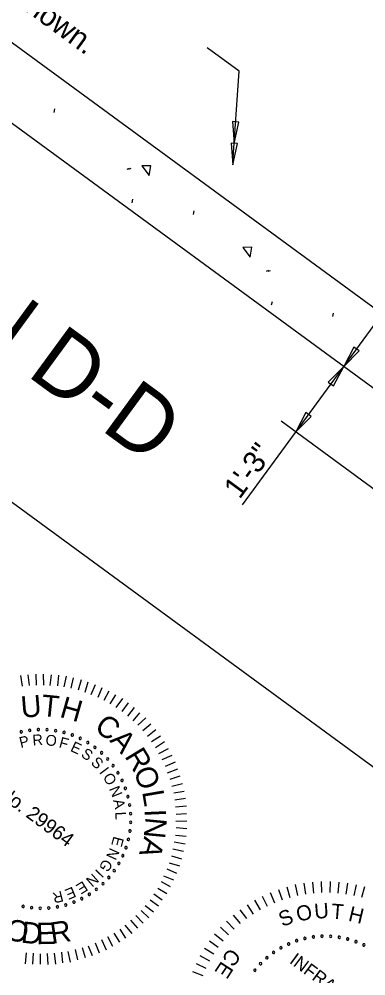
# Model space of a CAD drawing. Extents: x 1970731 to 1970899, y 796145 to 796301.
# Drawn here: x 1970813.63 to 1970821.64, y 796175.27 to 796197.36 of the extents above; entities that cross this region are included whole.
import ezdxf

# ---------------------------------------------------------------- set-up
doc = ezdxf.new("R2010")
doc.units = 0
for name, color, linetype in [('BR_AUTO DIMENSION', 7, 'Continuous'), ('BR_BORDER LINES', 7, 'Continuous'), ('BR_CONCRETE', 7, 'Continuous'), ('BR_DETAILS', 7, 'Continuous'), ('BR_TEXT', 7, 'Continuous')]:
    doc.layers.add(name, color=color, linetype=linetype)

msp = doc.modelspace()

# ---------------------------------------------------------------- linework, layer by layer
at = {"layer": 'BR_AUTO DIMENSION'}
for p, q in [((1970818.708, 796196.161), (1970817.972, 796196.699)), ((1970818.567, 796194.051), (1970818.708, 796196.16)), ((1970818.787, 796186.151), (1970823.376, 796192.419)), ((1970824.464, 796184.573), (1970819.679, 796188.077))]:
    msp.add_line(p, q, dxfattribs=at)
for points in [[(1970818.555, 796194.996), (1970818.596, 796194.492), (1970818.704, 796194.986)], [(1970818.522, 796194.501), (1970818.564, 796193.997), (1970818.672, 796194.491)], [(1970821.359, 796189.791), (1970821.124, 796189.343), (1970821.48, 796189.703)], [(1970820.889, 796188.895), (1970821.123, 796189.343), (1970820.768, 796188.984)], [(1970820.251, 796188.278), (1970820.016, 796187.831), (1970820.372, 796188.19)]]:
    msp.add_lwpolyline(points, close=True, dxfattribs=at)
at = {"layer": 'BR_BORDER LINES'}
msp.add_line((1970811.99, 796187.287), (1970829.306, 796174.609), dxfattribs=at)
at = {"layer": 'BR_CONCRETE'}
for p, q in [((1970827.934, 796186.216), (1970803.754, 796203.919)), ((1970827.073, 796184.987), (1970802.867, 796202.709)), ((1970827.073, 796184.987), (1970802.867, 796202.709))]:
    msp.add_line(p, q, dxfattribs=at)
at = {"layer": 'BR_DETAILS'}
for p, q in [((1970814.436, 796195.209), (1970814.453, 796195.289)), ((1970816.171, 796193.914), (1970816.114, 796193.894)), ((1970816.209, 796193.91), (1970816.153, 796193.889)), ((1970816.241, 796193.122), (1970816.258, 796193.202)), ((1970817.653, 796192.853), (1970817.671, 796192.933)), ((1970819.389, 796191.559), (1970819.332, 796191.538)), ((1970819.427, 796191.554), (1970819.37, 796191.534)), ((1970819.458, 796190.766), (1970819.476, 796190.846)), ((1970820.871, 796190.497), (1970820.888, 796190.577))]:
    msp.add_line(p, q, dxfattribs=at)
for points in [[(1970816.63, 796193.751), (1970816.672, 796193.978), (1970816.464, 796193.976), (1970816.63, 796193.751)], [(1970818.961, 796191.868), (1970819.004, 796192.095), (1970818.795, 796192.093), (1970818.961, 796191.868)]]:
    msp.add_lwpolyline(points, dxfattribs=at)
at = {"layer": 'BR_TEXT'}
for p, q in [((1970813.706, 796181.962), (1970813.668, 796182.209)), ((1970813.866, 796181.981), (1970813.837, 796182.224)), ((1970814.03, 796181.983), (1970814.019, 796182.239)), ((1970814.199, 796181.985), (1970814.193, 796182.242)), ((1970814.349, 796181.98), (1970814.379, 796182.227)), ((1970814.519, 796181.973), (1970814.549, 796182.22)), ((1970814.672, 796181.949), (1970814.72, 796182.191)), ((1970814.832, 796181.916), (1970814.888, 796182.152)), ((1970814.997, 796181.879), (1970815.067, 796182.117)), ((1970815.154, 796181.826), (1970815.22, 796182.063)), ((1970815.294, 796181.772), (1970815.396, 796182.001)), ((1970815.451, 796181.707), (1970815.546, 796181.932)), ((1970815.596, 796181.638), (1970815.711, 796181.855)), ((1970815.733, 796181.557), (1970815.865, 796181.763)), ((1970815.866, 796181.471), (1970816.02, 796181.677)), ((1970816.007, 796181.379), (1970816.154, 796181.577)), ((1970816.136, 796181.27), (1970816.295, 796181.472)), ((1970816.259, 796181.165), (1970816.418, 796181.35)), ((1970816.372, 796181.059), (1970816.551, 796181.23)), ((1970816.483, 796180.938), (1970816.669, 796181.095)), ((1970816.591, 796180.807), (1970816.786, 796180.965)), ((1970816.685, 796180.686), (1970816.891, 796180.819)), ((1970816.78, 796180.55), (1970816.989, 796180.686)), ((1970816.855, 796180.409), (1970817.076, 796180.522)), ((1970816.93, 796180.267), (1970817.162, 796180.373)), ((1970817.008, 796180.119), (1970817.239, 796180.217)), ((1970817.058, 796179.962), (1970817.294, 796180.056)), ((1970817.114, 796179.814), (1970817.35, 796179.89)), ((1970817.157, 796179.653), (1970817.405, 796179.716)), ((1970817.199, 796179.497), (1970817.443, 796179.538)), ((1970817.224, 796179.342), (1970817.467, 796179.379)), ((1970817.242, 796179.175), (1970817.493, 796179.197)), ((1970817.251, 796178.843), (1970817.502, 796178.852)), ((1970817.254, 796179.007), (1970817.495, 796179.021)), ((1970817.253, 796178.696), (1970817.498, 796178.675)), ((1970817.212, 796178.371), (1970817.462, 796178.321)), ((1970817.236, 796178.524), (1970817.483, 796178.499)), ((1970817.181, 796178.209), (1970817.423, 796178.154)), ((1970817.144, 796178.044), (1970817.377, 796177.978)), ((1970817.039, 796177.742), (1970817.266, 796177.645)), ((1970817.092, 796177.882), (1970817.33, 796177.816)), ((1970816.966, 796177.587), (1970817.196, 796177.493)), ((1970816.831, 796177.302), (1970817.043, 796177.178)), ((1970816.907, 796177.45), (1970817.116, 796177.334)), ((1970819.617, 796177.27), (1970819.7, 796177.03)), ((1970819.809, 796177.331), (1970819.878, 796177.086)), ((1970820.005, 796177.38), (1970820.059, 796177.131)), ((1970820.204, 796177.416), (1970820.243, 796177.164)), ((1970820.404, 796177.441), (1970820.428, 796177.187)), ((1970820.606, 796177.453), (1970820.614, 796177.198)), ((1970820.808, 796177.452), (1970820.8, 796177.198)), ((1970821.009, 796177.44), (1970820.986, 796177.186)), ((1970821.21, 796177.415), (1970821.171, 796177.163)), ((1970821.408, 796177.378), (1970821.354, 796177.129)), ((1970821.604, 796177.329), (1970821.535, 796177.084)), ((1970816.742, 796177.171), (1970816.935, 796177.028)), ((1970819.244, 796177.115), (1970819.357, 796176.886)), ((1970819.428, 796177.198), (1970819.526, 796176.964)), ((1970816.541, 796176.902), (1970816.73, 796176.752)), ((1970816.652, 796177.033), (1970816.847, 796176.888)), ((1970818.893, 796176.915), (1970819.033, 796176.702)), ((1970819.066, 796177.02), (1970819.192, 796176.799)), ((1970816.323, 796176.666), (1970816.49, 796176.494)), ((1970816.443, 796176.782), (1970816.62, 796176.611)), ((1970818.569, 796176.674), (1970818.734, 796176.48)), ((1970818.728, 796176.8), (1970818.88, 796176.596)), ((1970816.073, 796176.445), (1970816.231, 796176.255)), ((1970816.201, 796176.56), (1970816.361, 796176.372)), ((1970818.277, 796176.396), (1970818.464, 796176.223)), ((1970818.419, 796176.539), (1970818.595, 796176.355)), ((1970815.672, 796176.183), (1970815.788, 796175.96)), ((1970815.816, 796176.261), (1970815.946, 796176.056)), ((1970815.952, 796176.352), (1970816.085, 796176.146)), ((1970818.144, 796176.244), (1970818.341, 796176.082)), ((1970815.223, 796175.97), (1970815.315, 796175.743)), ((1970815.382, 796176.035), (1970815.477, 796175.806)), ((1970815.528, 796176.111), (1970815.641, 796175.877)), ((1970818.021, 796176.084), (1970818.228, 796175.935)), ((1970813.793, 796175.803), (1970813.765, 796175.554)), ((1970813.953, 796175.795), (1970813.935, 796175.547)), ((1970814.112, 796175.783), (1970814.113, 796175.543)), ((1970814.278, 796175.788), (1970814.294, 796175.54)), ((1970814.441, 796175.795), (1970814.468, 796175.544)), ((1970814.604, 796175.823), (1970814.633, 796175.575)), ((1970814.756, 796175.838), (1970814.809, 796175.593)), ((1970814.924, 796175.88), (1970814.979, 796175.643)), ((1970815.081, 796175.93), (1970815.15, 796175.695)), ((1970817.805, 796175.743), (1970818.028, 796175.62)), ((1970817.908, 796175.916), (1970818.123, 796175.78)), ((1970817.713, 796175.563), (1970817.943, 796175.454)), ((1970817.632, 796175.378), (1970817.868, 796175.283))]:
    msp.add_line(p, q, dxfattribs=at)
for centre, start, end in [((1970813.677, 796180.908), 13.1636, 193.1636), ((1970813.677, 796180.908), 193.1636, 13.1636), ((1970813.874, 796180.943), 7.6251, 187.6251), ((1970813.874, 796180.943), 187.6251, 7.6251), ((1970814.072, 796180.96), 2.0866, 182.0866), ((1970814.072, 796180.96), 182.0866, 2.0866), ((1970814.271, 796180.957), 356.5482, 176.5482), ((1970814.271, 796180.957), 176.5482, 356.5482), ((1970814.47, 796180.935), 351.0097, 171.0097), ((1970814.47, 796180.935), 171.0097, 351.0097), ((1970814.665, 796180.894), 345.4713, 165.4713), ((1970814.665, 796180.894), 165.4713, 345.4713), ((1970814.855, 796180.834), 159.9328, 339.9328), ((1970814.855, 796180.834), 339.9328, 159.9328), ((1970815.038, 796180.757), 154.3943, 334.3943), ((1970815.038, 796180.757), 334.3943, 154.3943), ((1970815.214, 796180.661), 148.8559, 328.8559), ((1970815.214, 796180.661), 328.8559, 148.8559), ((1970815.379, 796180.55), 323.3174, 143.3174), ((1970815.379, 796180.55), 143.3174, 323.3174), ((1970815.532, 796180.423), 137.779, 317.779), ((1970815.532, 796180.423), 317.779, 137.779), ((1970815.673, 796180.282), 132.2405, 312.2405), ((1970815.673, 796180.282), 312.2405, 132.2405), ((1970815.799, 796180.128), 126.702, 306.702), ((1970815.799, 796180.128), 306.702, 126.702), ((1970815.91, 796179.962), 121.1636, 301.1636), ((1970815.91, 796179.962), 301.1636, 121.1636), ((1970816.005, 796179.786), 115.6251, 295.6251), ((1970816.005, 796179.786), 295.6251, 115.6251), ((1970816.082, 796179.603), 110.0866, 290.0866), ((1970816.082, 796179.603), 290.0866, 110.0866), ((1970816.141, 796179.412), 104.5482, 284.5482), ((1970816.141, 796179.412), 284.5482, 104.5482), ((1970816.181, 796179.217), 99.0097, 279.0097), ((1970816.202, 796179.019), 93.4713, 273.4713), ((1970816.181, 796179.217), 279.0097, 99.0097), ((1970816.202, 796179.019), 273.4713, 93.4713), ((1970816.204, 796178.82), 87.9328, 267.9328), ((1970816.204, 796178.82), 267.9328, 87.9328), ((1970816.187, 796178.621), 82.3943, 262.3943), ((1970816.187, 796178.621), 262.3943, 82.3943), ((1970816.151, 796178.425), 76.8559, 256.8559), ((1970816.151, 796178.425), 256.8559, 76.8559), ((1970816.096, 796178.233), 71.3174, 251.3174), ((1970816.096, 796178.233), 251.3174, 71.3174), ((1970816.023, 796178.048), 65.779, 245.779), ((1970816.023, 796178.048), 245.779, 65.779), ((1970815.824, 796177.703), 54.702, 234.702), ((1970815.824, 796177.703), 234.702, 54.702), ((1970815.932, 796177.871), 60.2405, 240.2405), ((1970815.932, 796177.871), 240.2405, 60.2405), ((1970815.701, 796177.546), 49.1636, 229.1636), ((1970815.701, 796177.546), 229.1636, 49.1636), ((1970815.412, 796177.272), 38.0866, 218.0866), ((1970815.412, 796177.272), 218.0866, 38.0866), ((1970815.563, 796177.402), 43.6251, 223.6251), ((1970815.563, 796177.402), 223.6251, 43.6251), ((1970815.076, 796177.058), 27.0097, 207.0097), ((1970815.076, 796177.058), 207.0097, 27.0097), ((1970815.25, 796177.157), 32.5482, 212.5482), ((1970815.25, 796177.157), 212.5482, 32.5482), ((1970813.719, 796176.879), 348.2405, 168.2405), ((1970813.719, 796176.879), 168.2405, 348.2405), ((1970813.916, 796176.848), 353.779, 173.779), ((1970813.916, 796176.848), 173.779, 353.779), ((1970814.114, 796176.835), 359.3174, 179.3174), ((1970814.114, 796176.835), 179.3174, 359.3174), ((1970814.314, 796176.842), 4.8559, 184.8559), ((1970814.314, 796176.842), 184.8559, 4.8559), ((1970814.511, 796176.868), 10.3943, 190.3943), ((1970814.511, 796176.868), 190.3943, 10.3943), ((1970814.705, 796176.913), 15.9328, 195.9328), ((1970814.705, 796176.913), 195.9328, 15.9328), ((1970814.894, 796176.977), 21.4713, 201.4713), ((1970814.894, 796176.977), 201.4713, 21.4713), ((1970820.229, 796176.139), 13.1636, 193.1636), ((1970820.425, 796176.175), 7.6251, 187.6251), ((1970820.425, 796176.175), 187.6251, 7.6251), ((1970820.623, 796176.191), 2.0866, 182.0866), ((1970820.623, 796176.191), 182.0866, 2.0866), ((1970820.823, 796176.188), 356.5482, 176.5482), ((1970820.823, 796176.188), 176.5482, 356.5482), ((1970821.021, 796176.166), 351.0097, 171.0097), ((1970821.021, 796176.166), 171.0097, 351.0097), ((1970819.673, 796175.922), 29.779, 209.779), ((1970819.673, 796175.922), 209.779, 29.779), ((1970819.851, 796176.012), 24.2405, 204.2405), ((1970819.851, 796176.012), 204.2405, 24.2405), ((1970820.037, 796176.085), 18.702, 198.702), ((1970820.037, 796176.085), 198.702, 18.702), ((1970820.229, 796176.139), 193.1636, 13.1636), ((1970821.216, 796176.125), 165.4713, 345.4713), ((1970821.216, 796176.125), 345.4713, 165.4713), ((1970821.406, 796176.066), 159.9328, 339.9328), ((1970821.406, 796176.066), 339.9328, 159.9328), ((1970821.589, 796175.988), 154.3943, 334.3943), ((1970821.589, 796175.988), 334.3943, 154.3943), ((1970819.348, 796175.692), 40.8559, 220.8559), ((1970819.505, 796175.815), 35.3174, 215.3174), ((1970819.505, 796175.815), 215.3174, 35.3174), ((1970819.203, 796175.555), 46.3943, 226.3943), ((1970819.203, 796175.555), 226.3943, 46.3943), ((1970819.348, 796175.692), 220.8559, 40.8559), ((1970819.073, 796175.405), 51.9328, 231.9328), ((1970819.073, 796175.405), 231.9328, 51.9328)]:
    msp.add_arc(centre, 0.028, start, end, dxfattribs=at)

# ---------------------------------------------------------------- texts
at = {"layer": 'BR_AUTO DIMENSION'}
msp.add_text('1\'-3"', height=0.5, rotation=53.7906, dxfattribs=at).set_placement((1970818.72, 796186.261))
at = {"layer": 'BR_TEXT'}
for s, height, rotation, p in [('DEFLECTION JOINT DETAIL', 1.5, 323.7906, (1970813.588, 796212.86)), ('Reinforcing not shown. ', 0.49995, 323.7906, (1970809.688, 796200.537)), ('SECTION D-D', 1.5, 323.7906, (1970806.131, 796194.749)), ('U', 0.496, 4.5928, (1970813.685, 796181.23)), ('T', 0.496, 354.2898, (1970814.124, 796181.279)), ('H', 0.496, 344.1543, (1970814.543, 796181.257)), ('C', 0.496, 323.3388, (1970815.341, 796180.962)), ('P', 0.249, 13.7327, (1970813.666, 796180.534)), ('R', 0.249, 4.1855, (1970813.945, 796180.59)), ('O', 0.249, 354.6383, (1970814.23, 796180.599)), ('A', 0.496, 311.9887, (1970815.703, 796180.701)), ('F', 0.249, 344.4033, (1970814.533, 796180.556)), ('E', 0.249, 335.2009, (1970814.794, 796180.472)), ('S', 0.249, 325.9986, (1970815.039, 796180.348)), ('R', 0.496, 301.225, (1970816.053, 796180.346)), ('S', 0.249, 316.4514, (1970815.269, 796180.179)), ('I', 0.249, 306.9042, (1970815.467, 796179.974)), ('O', 0.249, 302.2298, (1970815.551, 796179.862)), ('O', 0.496, 290.3775, (1970816.264, 796180.009)), ('No. 29964', 0.327, 323.3174, (1970813.121, 796179.439)), ('N', 0.249, 291.9947, (1970815.701, 796179.596)), ('L', 0.496, 279.7394, (1970816.467, 796179.525)), ('A', 0.249, 282.4476, (1970815.797, 796179.328)), ('L', 0.249, 273.2452, (1970815.846, 796179.057)), ('I', 0.496, 272.4519, (1970816.522, 796179.116)), ('N', 0.496, 264.4942, (1970816.551, 796178.949)), ('E', 0.249, 254.8396, (1970815.812, 796178.511)), ('A', 0.496, 253.2698, (1970816.523, 796178.509)), ('N', 0.249, 245.6372, (1970815.73, 796178.248)), ('G', 0.249, 236.09, (1970815.602, 796177.994)), ('I', 0.249, 226.1989, (1970815.426, 796177.756)), ('N', 0.249, 221.5245, (1970815.33, 796177.655)), ('E', 0.249, 202.775, (1970814.87, 796177.339)), ('E', 0.249, 211.9773, (1970815.109, 796177.475)), ('R', 0.249, 193.5726, (1970814.613, 796177.242)), ('O', 0.349, 13.6688, (1970820.073, 796176.518)), ('U', 0.349, 4.6388, (1970820.457, 796176.589)), ('T', 0.349, 355.6088, (1970820.826, 796176.597)), ('H', 0.349, 346.5788, (1970821.212, 796176.55)), ('S', 0.349, 22.6989, (1970819.709, 796176.397)), ('O', 0.494, 346.2118, (1970813.281, 796176.135)), ('D', 0.494, 353.892, (1970813.657, 796176.044)), ('E', 0.494, 1.3245, (1970814.029, 796176.004)), ('R', 0.494, 8.3853, (1970814.384, 796176.011)), ('C', 0.349, 230.8156, (1970818.506, 796175.939)), ('INFRASTRUCTURE', 0.29909, 323.3174, (1970819.852, 796175.586)), ('E', 0.349, 236.8156, (1970818.304, 796175.633))]:
    msp.add_text(s, height=height, rotation=rotation, dxfattribs=at).set_placement(p)

doc.saveas('drawing.dxf')
